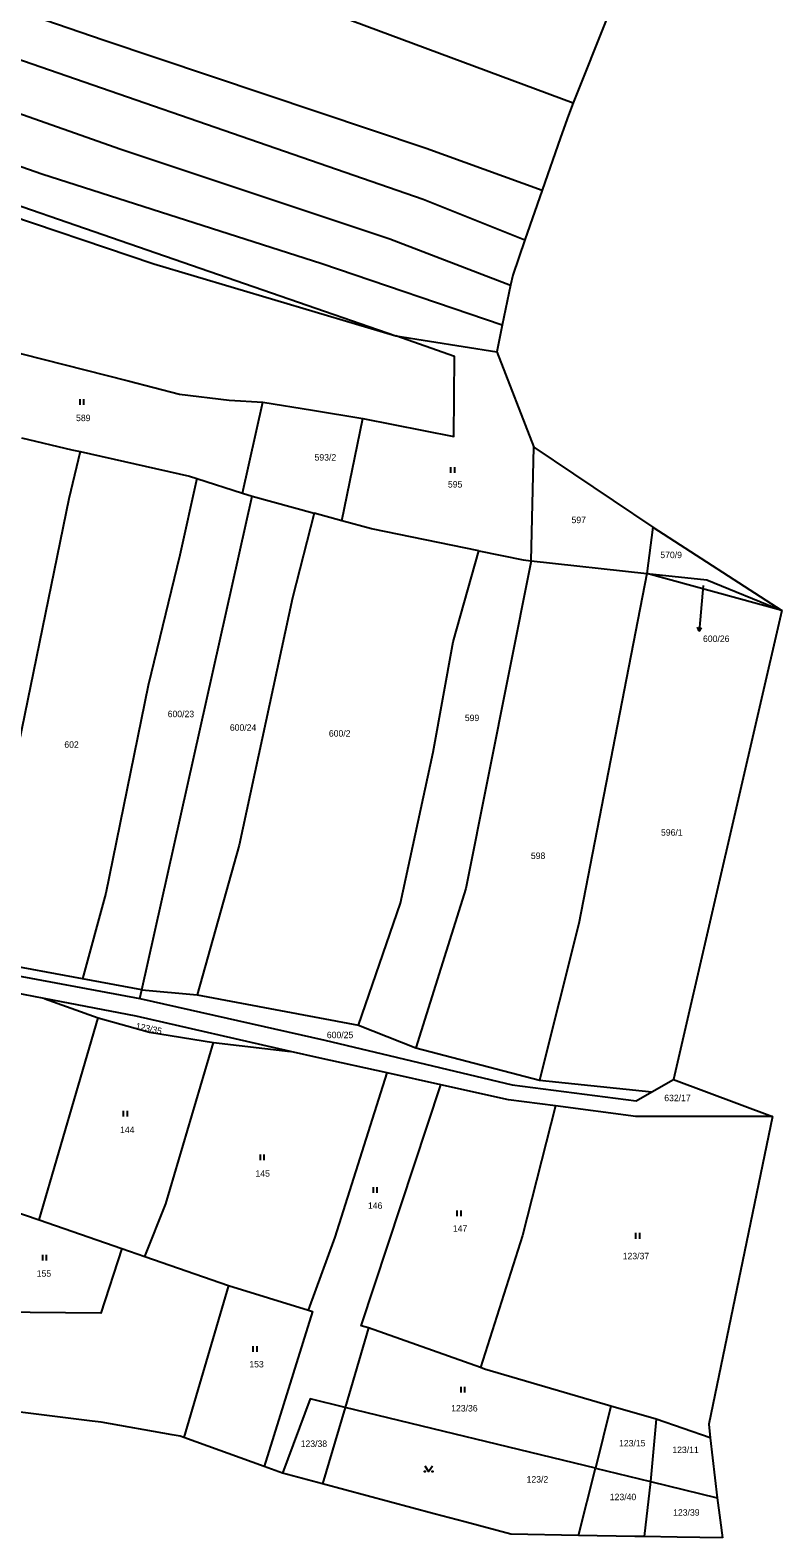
# Model space of a CAD drawing. Extents: x -746176 to -739709, y -1128407 to -1124482.
# Drawn here: x -742205.8 to -742008.1, y -1127528.4 to -1127131.5 of the extents above; entities that cross this region are included whole.
import ezdxf

# ---------------------------------------------------------------- set-up
doc = ezdxf.new("R2010")
doc.units = 0
for name, color, linetype in [('Hranice parcel', 7, 'Continuous'), ('Parcelní čísla', 7, 'Continuous'), ('Pop  PČ popisy', 7, 'Continuous'), ('Značky kultur', 7, 'Continuous')]:
    doc.layers.add(name, color=color, linetype=linetype)

msp = doc.modelspace()

# ---------------------------------------------------------------- linework, layer by layer
at = {"layer": 'Hranice parcel'}
for p, q in [((-742053.72, -1127127.51), (-742062.93, -1127150.64)), ((-742066.27, -1127159.76), (-742071.1, -1127173.63)), ((-742071.1, -1127173.63), (-742075.64, -1127186.64)), ((-742079.42, -1127198.6), (-742081.6, -1127209.14)), ((-742081.6, -1127209.14), (-742083.06, -1127216.18)), ((-742109.57, -1127211.92), (-742083.06, -1127216.18)), ((-742083.06, -1127216.18), (-742073.31, -1127241.28)), ((-742149.95, -1127253.34), (-742144.62, -1127229.42)), ((-742123.8, -1127260.63), (-742118.26, -1127233.67)), ((-742073.98, -1127271.14), (-742073.31, -1127241.28)), ((-742073.31, -1127241.28), (-742042.05, -1127262.32)), ((-742161.94, -1127249.48), (-742149.95, -1127253.34)), ((-742149.95, -1127253.34), (-742147.38, -1127254.17)), ((-742176.39, -1127384.12), (-742147.38, -1127254.17)), ((-742147.38, -1127254.17), (-742131.09, -1127258.63)), ((-742123.8, -1127260.63), (-742131.09, -1127258.63)), ((-742042.05, -1127262.32), (-742043.59, -1127274.46)), ((-742042.05, -1127262.32), (-742008.08, -1127284.25)), ((-742073.98, -1127271.14), (-742043.59, -1127274.46)), ((-742008.08, -1127284.25), (-742043.59, -1127274.46)), ((-742192.07, -1127381.21), (-742222.79, -1127375.51)), ((-742176.39, -1127384.12), (-742192.07, -1127381.21)), ((-742176.91, -1127386.35), (-742176.39, -1127384.12)), ((-742176.39, -1127384.12), (-742161.84, -1127385.41)), ((-742202.09, -1127386.37), (-742187.88, -1127391.48)), ((-742161.84, -1127385.41), (-742119.42, -1127393.4)), ((-742203.39, -1127444.64), (-742187.88, -1127391.48)), ((-742119.42, -1127393.4), (-742104.38, -1127399.34)), ((-742157.54, -1127397.98), (-742137.29, -1127400.3)), ((-742104.38, -1127399.34), (-742071.83, -1127407.9)), ((-742097.77, -1127409.1), (-742111.92, -1127405.97)), ((-742071.83, -1127407.9), (-742042.25, -1127410.93)), ((-742042.25, -1127410.93), (-742036.58, -1127407.72)), ((-742036.58, -1127407.72), (-742010.57, -1127417.44)), ((-742010.57, -1127417.44), (-742027.32, -1127498.39)), ((-742217.73, -1127439.8), (-742203.39, -1127444.64)), ((-742203.39, -1127444.64), (-742181.67, -1127452.16)), ((-742181.67, -1127452.16), (-742175.63, -1127454.26)), ((-742175.63, -1127454.26), (-742153.67, -1127461.89)), ((-742153.67, -1127461.89), (-742165.38, -1127501.9)), ((-742153.67, -1127461.89), (-742132.57, -1127468.42)), ((-742116.77, -1127473.1), (-742122.96, -1127494.02)), ((-742087.32, -1127483.52), (-742116.77, -1127473.1)), ((-742189.51, -1127497.64), (-742238.51, -1127491.51)), ((-742122.96, -1127494.02), (-742128.92, -1127514.16)), ((-742057.12, -1127510.01), (-742122.96, -1127494.02)), ((-742053.04, -1127493.66), (-742057.12, -1127510.01)), ((-742041.17, -1127497.12), (-742053.04, -1127493.66)), ((-742041.17, -1127497.12), (-742042.61, -1127513.54)), ((-742026.89, -1127502.06), (-742041.17, -1127497.12)), ((-742027.32, -1127498.39), (-742026.89, -1127502.06)), ((-742144.27, -1127509.6), (-742165.38, -1127501.9)), ((-742026.89, -1127502.06), (-742025.05, -1127517.8)), ((-742139.43, -1127511.36), (-742144.27, -1127509.6)), ((-742128.92, -1127514.16), (-742139.43, -1127511.36)), ((-742061.59, -1127527.72), (-742057.12, -1127510.01)), ((-742057.12, -1127510.01), (-742042.61, -1127513.54)), ((-742099.57, -1127521.99), (-742128.92, -1127514.16)), ((-742042.61, -1127513.54), (-742044.27, -1127528.03)), ((-742042.61, -1127513.54), (-742025.05, -1127517.8)), ((-742025.05, -1127517.8), (-742024.3, -1127523.72)), ((-742091.44, -1127524.16), (-742099.57, -1127521.99)), ((-742024.3, -1127523.72), (-742023.72, -1127528.35)), ((-742035.6, -1127528.16), (-742044.27, -1127528.03)), ((-742023.72, -1127528.35), (-742035.6, -1127528.16))]:
    msp.add_line(p, q, dxfattribs=at)
for points in [[(-742527.24, -1126986.86), (-742482.52, -1127005.44), (-742410.26, -1127030.86), (-742263.45, -1127080.11), (-742124.08, -1127127.86), (-742062.93, -1127150.64)], [(-742540.51, -1127007.89), (-742508.14, -1127021.79), (-742465.67, -1127038.76), (-742304.51, -1127093.48), (-742186.57, -1127134.04), (-742101.64, -1127162.49), (-742071.1, -1127173.63)], [(-742548.14, -1127019.47), (-742535.36, -1127026.31), (-742485.61, -1127044.66), (-742396.17, -1127075.85), (-742237.29, -1127129.3), (-742102.44, -1127175.98), (-742075.64, -1127186.64)], [(-742556.03, -1127030.18), (-742540.54, -1127037.88), (-742464.14, -1127065.48), (-742257.87, -1127136.04), (-742181.95, -1127162.82), (-742111.16, -1127186.39), (-742079.42, -1127198.6)], [(-742081.6, -1127209.14), (-742129.12, -1127193.01), (-742202.75, -1127169.34), (-742345.7, -1127119.16), (-742474.83, -1127076.87), (-742507.28, -1127063.47), (-742545.28, -1127047.75), (-742563.37, -1127039.11)], [(-742391.64, -1127117.14), (-742294.31, -1127148.02), (-742109.57, -1127211.92)], [(-742391.64, -1127117.14), (-742217.48, -1127178.02), (-742173.31, -1127193), (-742109.57, -1127211.92)], [(-742062.93, -1127150.64), (-742064.2, -1127153.82), (-742066.27, -1127159.76)], [(-742075.64, -1127186.64), (-742078.87, -1127195.92), (-742079.42, -1127198.6)], [(-742229.11, -1127210.34), (-742207.95, -1127216.71), (-742180, -1127223.79), (-742166.56, -1127227.33), (-742153.47, -1127228.89), (-742144.62, -1127229.42)], [(-742118.26, -1127233.67), (-742094.37, -1127238.45), (-742094.19, -1127217.4), (-742109.57, -1127211.92)], [(-742144.62, -1127229.42), (-742131.53, -1127231.54), (-742118.26, -1127233.67)], [(-742208.04, -1127238.77), (-742194.8, -1127241.9), (-742192.66, -1127242.38)], [(-742192.66, -1127242.38), (-742195.66, -1127254.86), (-742215.86, -1127353.44), (-742222.79, -1127375.51)], [(-742192.66, -1127242.38), (-742163.93, -1127248.84), (-742161.94, -1127249.48)], [(-742161.94, -1127249.48), (-742166.42, -1127269.64), (-742174.74, -1127303.95), (-742185.93, -1127358.67), (-742192.07, -1127381.21)], [(-742131.09, -1127258.63), (-742136.83, -1127280.94), (-742150.79, -1127346.02), (-742161.84, -1127385.41)], [(-742087.75, -1127268.53), (-742116.02, -1127262.76), (-742123.8, -1127260.63)], [(-742119.42, -1127393.4), (-742108.38, -1127361.31), (-742099.75, -1127321.56), (-742094.55, -1127292.44), (-742087.75, -1127268.53)], [(-742087.75, -1127268.53), (-742076.13, -1127270.9), (-742073.98, -1127271.14)], [(-742073.98, -1127271.14), (-742091.23, -1127357.45), (-742104.38, -1127399.34)], [(-742482.5, -1127277.19), (-742478.71, -1127279.87), (-742435.6, -1127297.95), (-742390.76, -1127324.91), (-742338.36, -1127352.64), (-742294.93, -1127366.2), (-742262.34, -1127370.73), (-742214.62, -1127379.37), (-742176.91, -1127386.35)], [(-742043.59, -1127274.46), (-742061.45, -1127366.63), (-742071.83, -1127407.9)], [(-742043.59, -1127274.46), (-742027.79, -1127276.18), (-742008.08, -1127284.25)], [(-742008.08, -1127284.25), (-742025.96, -1127361.68), (-742036.58, -1127407.72)], [(-742202.09, -1127386.37), (-742215.77, -1127383.71), (-742217.46, -1127383.38)], [(-742137.29, -1127400.3), (-742177.91, -1127391.06), (-742202.09, -1127386.37)], [(-742176.91, -1127386.35), (-742128.3, -1127397.32), (-742079.03, -1127409.11), (-742046.4, -1127413.28), (-742042.25, -1127410.93)], [(-742187.88, -1127391.48), (-742174.45, -1127395.26), (-742157.54, -1127397.98)], [(-742175.63, -1127454.26), (-742170.07, -1127440.42), (-742157.54, -1127397.98)], [(-742111.92, -1127405.97), (-742129.55, -1127402.06), (-742137.29, -1127400.3)], [(-742132.57, -1127468.42), (-742125.56, -1127449.24), (-742111.92, -1127405.97)], [(-742116.77, -1127473.1), (-742118.71, -1127472.53), (-742097.77, -1127409.1)], [(-742067.59, -1127414.66), (-742079.94, -1127413.05), (-742097.77, -1127409.1)], [(-742067.59, -1127414.66), (-742076.25, -1127448.77), (-742087.32, -1127483.52)], [(-742010.57, -1127417.44), (-742046.51, -1127417.4), (-742067.59, -1127414.66)], [(-742181.67, -1127452.16), (-742187.21, -1127469.19), (-742224.46, -1127468.86)], [(-742132.57, -1127468.42), (-742131.55, -1127468.74), (-742144.27, -1127509.6)], [(-742053.04, -1127493.66), (-742086.26, -1127483.91), (-742087.32, -1127483.52)], [(-742122.96, -1127494.02), (-742132.12, -1127491.8), (-742139.43, -1127511.36)], [(-742168.46, -1127501.19), (-742187.15, -1127497.94), (-742189.51, -1127497.64)], [(-742165.38, -1127501.9), (-742166.32, -1127501.56), (-742168.46, -1127501.19)], [(-742061.59, -1127527.72), (-742079.34, -1127527.39), (-742091.44, -1127524.16)], [(-742044.27, -1127528.03), (-742046.73, -1127527.99), (-742061.59, -1127527.72)]]:
    msp.add_lwpolyline(points, dxfattribs=at)
at = {"layer": 'Pop  PČ popisy'}
for p, q in [((-742028.77, -1127277.65), (-742029.55, -1127286.7)), ((-742029.81, -1127289.69), (-742030.22, -1127288.65)), ((-742029.55, -1127286.7), (-742029.81, -1127289.69)), ((-742029.81, -1127289.69), (-742029.22, -1127288.74))]:
    msp.add_line(p, q, dxfattribs=at)
at = {"layer": 'Značky kultur'}
for p, q in [((-742192.67, -1127230.08), (-742192.67, -1127228.58)), ((-742191.67, -1127230.08), (-742191.67, -1127228.58)), ((-742095.12, -1127247.97), (-742095.12, -1127246.47)), ((-742094.12, -1127247.97), (-742094.12, -1127246.47)), ((-742181.22, -1127417.4), (-742181.22, -1127415.9)), ((-742180.22, -1127417.4), (-742180.22, -1127415.9)), ((-742145.25, -1127428.96), (-742145.25, -1127427.46)), ((-742144.25, -1127428.96), (-742144.25, -1127427.46)), ((-742115.51, -1127437.57), (-742115.51, -1127436.07)), ((-742114.51, -1127437.57), (-742114.51, -1127436.07)), ((-742093.47, -1127443.7), (-742093.47, -1127442.2)), ((-742092.47, -1127443.7), (-742092.47, -1127442.2)), ((-742046.45, -1127449.6), (-742046.45, -1127448.1)), ((-742045.45, -1127449.6), (-742045.45, -1127448.1)), ((-742202.47, -1127455.31), (-742202.47, -1127453.81)), ((-742201.47, -1127455.31), (-742201.47, -1127453.81)), ((-742147.13, -1127479.36), (-742147.13, -1127477.86)), ((-742146.13, -1127479.36), (-742146.13, -1127477.86)), ((-742092.45, -1127490.09), (-742092.45, -1127488.59)), ((-742091.45, -1127490.09), (-742091.45, -1127488.59))]:
    msp.add_line(p, q, dxfattribs=at)
msp.add_lwpolyline([(-742101.99, -1127509.39), (-742100.99, -1127510.89), (-742099.99, -1127509.39)], dxfattribs=at)
for centre in [(-742101.99, -1127510.89), (-742099.99, -1127510.89)]:
    msp.add_circle(centre, 0.1, dxfattribs=at)

# ---------------------------------------------------------------- texts
at = {"layer": 'Parcelní čísla'}
for s, p in [('589', (-742193.72, -1127234.39)), ('593/2', (-742130.99, -1127244.77)), ('595', (-742095.91, -1127251.87)), ('597', (-742063.4, -1127261.24)), ('570/9', (-742040.04, -1127270.45)), ('600/26', (-742028.81, -1127292.52)), ('600/23', (-742169.62, -1127312.32)), ('599', (-742091.46, -1127313.35)), ('600/24', (-742153.27, -1127315.9)), ('600/2', (-742127.22, -1127317.44)), ('602', (-742196.81, -1127320.37)), ('596/1', (-742039.86, -1127343.51)), ('598', (-742074.09, -1127349.64)), ('600/25', (-742127.76, -1127396.82)), ('632/17', (-742039, -1127413.4)), ('144', (-742182.15, -1127421.79)), ('145', (-742146.53, -1127433.27)), ('146', (-742116.95, -1127441.73)), ('147', (-742094.61, -1127447.77)), ('123/37', (-742049.93, -1127455.02)), ('155', (-742204.07, -1127459.61)), ('153', (-742148.15, -1127483.49)), ('123/36', (-742095.05, -1127495.09)), ('123/38', (-742134.64, -1127504.42)), ('123/15', (-742050.9, -1127504.28)), ('123/11', (-742036.88, -1127506.03)), ('123/2', (-742075.21, -1127513.79)), ('123/40', (-742053.33, -1127518.44)), ('123/39', (-742036.67, -1127522.52))]:
    msp.add_text(s, height=1.7, dxfattribs=at).set_placement(p)
msp.add_text('123/35', height=1.7, rotation=348, dxfattribs=at).set_placement((-742178.15, -1127394.39))

doc.saveas('drawing.dxf')
